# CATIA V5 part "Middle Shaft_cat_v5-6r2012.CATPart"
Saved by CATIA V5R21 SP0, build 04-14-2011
Part number: Middle shaft
Bounding box of the stored display mesh (mm): x 0 to 100, y -25 to 25, z -24.818 to 24.818
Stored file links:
  D:\CATIA V5R21 E-RESOURCES\CATIA-V5R21\catia-v5r21-Tut\c16-catia-v5r21-tut\c16-catia-v5r21-tut02\Middle Shaft_cat_v5r21.CATPart
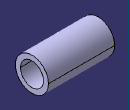
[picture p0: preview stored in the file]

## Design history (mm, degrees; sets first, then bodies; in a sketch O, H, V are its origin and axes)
Body1 (main body)
  Sketch1 on yz-plane, origin (0, 0, 0), H (0, 1, 0), V (0, 0, 1)
    circle A1 centre (0, 0) radius 25
    circle A2 centre (0, 0) radius 17.5
    radius A1 = 25
    radius A2 = 17.5
  Pad1: profile Sketch1, direction (1, 0, 0), length 100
